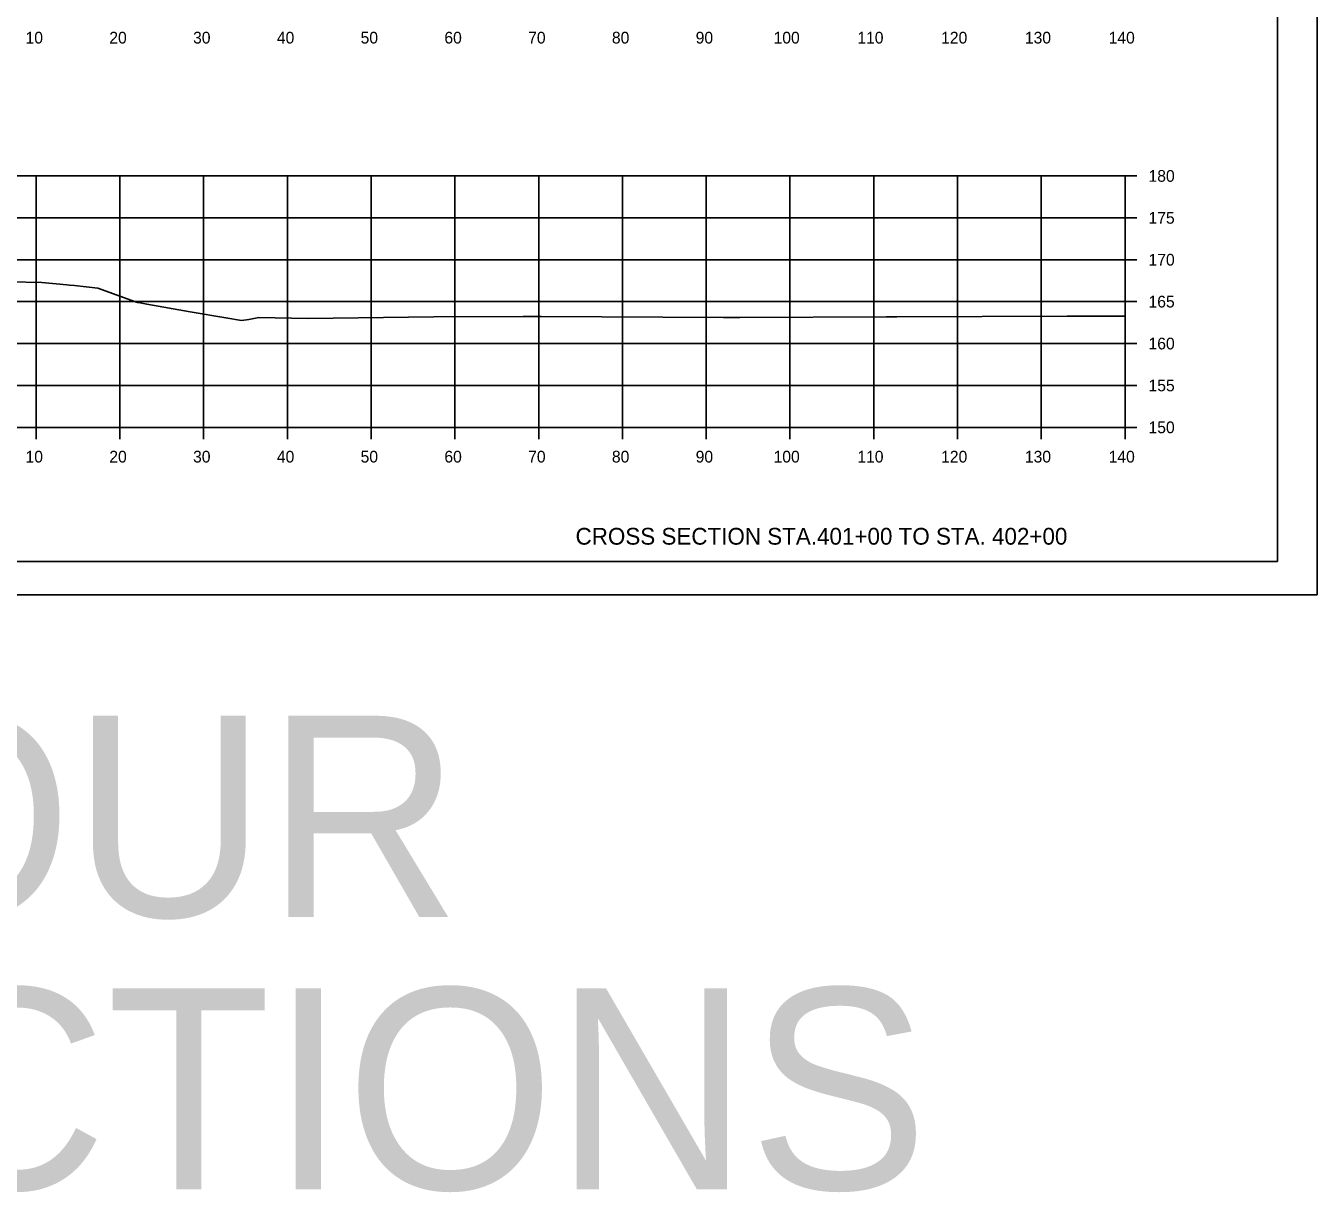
# Model space of a CAD drawing. Extents: x 1368503 to 1373085, y 379840 to 381833.
# Drawn here: x 1372930.9 to 1373085, y 379890.3 to 380029.5 of the extents above; entities that cross this region are included whole.
import ezdxf

# ---------------------------------------------------------------- set-up
doc = ezdxf.new("R2010")
doc.units = 0
for name, color, linetype in [('S_BRIDGE', 7, 'Continuous'), ('S_EDGE_PAVEMENT', 7, 'Continuous'), ('S_MISC_BOUNDARY', 7, 'Continuous'), ('S_PHOTO_CENTERS', 7, 'Continuous'), ('S_PHOTO_NOTES', 7, 'Continuous'), ('S_TRAILS', 7, 'Continuous'), ('S_TREE', 7, 'Continuous')]:
    doc.layers.add(name, color=color, linetype=linetype)

msp = doc.modelspace()

# ---------------------------------------------------------------- linework, layer by layer
at = {"layer": 'S_BRIDGE'}
for q in [(1373080.26, 380171.07), (1372764.08, 379965.61)]:
    msp.add_line((1373080.26, 379965.61), q, dxfattribs=at)
at = {"layer": 'S_EDGE_PAVEMENT'}
for p, q in [((1373062.08, 379981.61), (1373062.08, 380011.61)), ((1373063.48, 380011.61), (1373062.08, 380011.61)), ((1373063.48, 380006.61), (1373062.08, 380006.61)), ((1373063.48, 380001.61), (1373062.08, 380001.61)), ((1373063.48, 379996.61), (1373062.08, 379996.61)), ((1373063.48, 379991.61), (1373062.08, 379991.61)), ((1373063.48, 379986.61), (1373062.08, 379986.61)), ((1372782.08, 379981.61), (1373062.08, 379981.61)), ((1372932.08, 379980.21), (1372932.08, 379981.61)), ((1372942.08, 379980.21), (1372942.08, 379981.61)), ((1372952.08, 379980.21), (1372952.08, 379981.61)), ((1372962.08, 379980.21), (1372962.08, 379981.61)), ((1372972.08, 379980.21), (1372972.08, 379981.61)), ((1372982.08, 379980.21), (1372982.08, 379981.61)), ((1372992.08, 379980.21), (1372992.08, 379981.61)), ((1373002.08, 379980.21), (1373002.08, 379981.61)), ((1373012.08, 379980.21), (1373012.08, 379981.61)), ((1373022.08, 379980.21), (1373022.08, 379981.61)), ((1373032.08, 379980.21), (1373032.08, 379981.61)), ((1373042.08, 379980.21), (1373042.08, 379981.61)), ((1373052.08, 379980.21), (1373052.08, 379981.61)), ((1373062.08, 379980.21), (1373062.08, 379981.61)), ((1373063.48, 379981.61), (1373062.08, 379981.61))]:
    msp.add_line(p, q, dxfattribs=at)
at = {"layer": 'S_MISC_BOUNDARY'}
msp.add_lwpolyline([(1372925.16, 379999.06), (1372932.76, 379998.91), (1372935.73, 379998.61), (1372936.08, 379998.58), (1372936.66, 379998.52), (1372939.46, 379998.2), (1372943.93, 379996.6), (1372944.18, 379996.51), (1372944.29, 379996.49), (1372945.28, 379996.31), (1372950.49, 379995.39), (1372954.74, 379994.69), (1372956.62, 379994.37), (1372957.47, 379994.47), (1372958.69, 379994.71), (1372964.53, 379994.6), (1372979.55, 379994.81), (1372990.22, 379994.85), (1372992.38, 379994.85), (1373014.16, 379994.72), (1373016.09, 379994.73), (1373033.57, 379994.79), (1373034.82, 379994.8), (1373055.15, 379994.88), (1373056.29, 379994.88), (1373062.08, 379994.89)], dxfattribs=at)
at = {"layer": 'S_PHOTO_CENTERS'}
for p, q in [((1372782.08, 380011.61), (1373062.08, 380011.61)), ((1372932.08, 379981.61), (1372932.08, 380011.61)), ((1372942.08, 379981.61), (1372942.08, 380011.61)), ((1372952.08, 379981.61), (1372952.08, 380011.61)), ((1372962.08, 379981.61), (1372962.08, 380011.61)), ((1372972.08, 379981.61), (1372972.08, 380011.61)), ((1372982.08, 379981.61), (1372982.08, 380011.61)), ((1372992.08, 379981.61), (1372992.08, 380011.61)), ((1373002.08, 379981.61), (1373002.08, 380011.61)), ((1373012.08, 379981.61), (1373012.08, 380011.61)), ((1373022.08, 379981.61), (1373022.08, 380011.61)), ((1373032.08, 379981.61), (1373032.08, 380011.61)), ((1373042.08, 379981.61), (1373042.08, 380011.61)), ((1373052.08, 379981.61), (1373052.08, 380011.61)), ((1373062.08, 379981.61), (1373062.08, 380011.61)), ((1372782.08, 380006.61), (1373062.08, 380006.61)), ((1372782.08, 380001.61), (1373062.08, 380001.61)), ((1372782.08, 379996.61), (1373062.08, 379996.61)), ((1372782.08, 379991.61), (1373062.08, 379991.61)), ((1372782.08, 379986.61), (1373062.08, 379986.61)), ((1372782.08, 379981.61), (1373062.08, 379981.61))]:
    msp.add_line(p, q, dxfattribs=at)
at = {"layer": 'S_PHOTO_NOTES'}
msp.add_line((1372751.68, 379961.63), (1373085.01, 379961.63), dxfattribs=at)
for points in [[(1372751.67, 380174.97), (1373085.01, 380174.97), (1373085.01, 379961.63), (1372751.67, 379961.63)], [(1372998, 380171.07), (1372998, 380161.19), (1373033.73, 380161.19), (1373033.73, 380158.27), (1373056.93, 380158.27), (1373056.93, 380133.94), (1373080.26, 380133.94), (1373080.26, 379965.61), (1372764.08, 379965.61), (1372764.08, 380171.07)]]:
    msp.add_lwpolyline(points, close=True, dxfattribs=at)

# ---------------------------------------------------------------- texts
for s, p in [('DETOUR', (1372847.25, 379923.19)), ('CROSS SECTIONS', (1372751.48, 379890.68))]:
    msp.add_text(s, height=24, dxfattribs=at).set_placement(p)
at = {"layer": 'S_TRAILS'}
for s, p in [('10', (1372930.82, 380027.41)), ('20', (1372940.82, 380027.41)), ('30', (1372950.82, 380027.41)), ('40', (1372960.82, 380027.41)), ('50', (1372970.82, 380027.41)), ('60', (1372980.82, 380027.41)), ('70', (1372990.82, 380027.41)), ('80', (1373000.82, 380027.41)), ('90', (1373010.82, 380027.41)), ('100', (1373020.12, 380027.41)), ('110', (1373030.12, 380027.41)), ('120', (1373040.12, 380027.41)), ('130', (1373050.12, 380027.41)), ('140', (1373060.12, 380027.41)), ('180', (1373064.88, 380010.91)), ('175', (1373064.88, 380005.91)), ('170', (1373064.88, 380000.91)), ('165', (1373064.88, 379995.91)), ('160', (1373064.88, 379990.91)), ('155', (1373064.88, 379985.91)), ('150', (1373064.88, 379980.91)), ('10', (1372930.82, 379977.41)), ('20', (1372940.82, 379977.41)), ('30', (1372950.82, 379977.41)), ('40', (1372960.82, 379977.41)), ('50', (1372970.82, 379977.41)), ('60', (1372980.82, 379977.41)), ('70', (1372990.82, 379977.41)), ('80', (1373000.82, 379977.41)), ('90', (1373010.82, 379977.41)), ('100', (1373020.12, 379977.41)), ('110', (1373030.12, 379977.41)), ('120', (1373040.12, 379977.41)), ('130', (1373050.12, 379977.41)), ('140', (1373060.12, 379977.41))]:
    msp.add_text(s, height=1.4, dxfattribs=at).set_placement(p)
at = {"layer": 'S_TREE'}
msp.add_text('CROSS SECTION STA.401+00 TO STA. 402+00', height=2, dxfattribs=at).set_placement((1372996.48, 379967.61))

doc.saveas('drawing.dxf')
